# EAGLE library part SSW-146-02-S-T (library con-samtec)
THROUGH-HOLE .025" SQ POST SOCKET Source: Samtec SSW.pdf
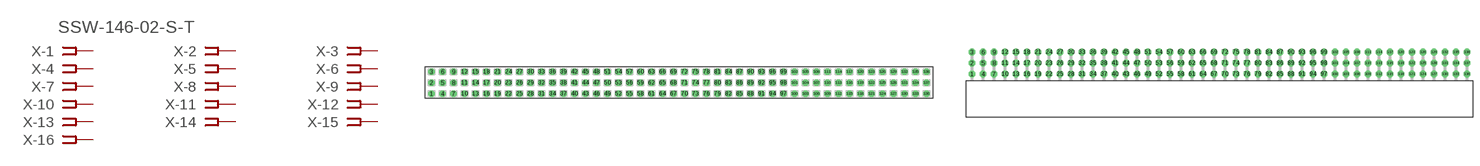
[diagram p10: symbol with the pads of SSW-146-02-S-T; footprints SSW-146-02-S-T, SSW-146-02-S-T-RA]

Designator prefix X; gates -1=FPINV -2=FPIN -3=FPIN -4=FPIN -5=FPIN -6=FPIN -7=FPIN -8=FPIN -9=FPIN -10=FPIN -11=FPIN -12=FPIN -13=FPIN -14=FPIN -15=FPIN -16=FPIN -17=FPIN -18=FPIN -19=FPIN -20=FPIN -21=FPIN -22=FPIN -23=FPIN -24=FPIN -25=FPIN -26=FPIN -27=FPIN -28=FPIN -29=FPIN -30=FPIN -31=FPIN -32=FPIN -33=FPIN -34=FPIN -35=FPIN -36=FPIN -37=FPIN -38=FPIN -39=FPIN -40=FPIN -41=FPIN -42=FPIN -43=FPIN -44=FPIN -45=FPIN -46=FPIN -47=FPIN -48=FPIN -49=FPIN -50=FPIN -51=FPIN -52=FPIN -53=FPIN -54=FPIN -55=FPIN -56=FPIN -57=FPIN -58=FPIN -59=FPIN -60=FPIN -61=FPIN -62=FPIN -63=FPIN -64=FPIN -65=FPIN -66=FPIN -67=FPIN -68=FPIN -69=FPIN -70=FPIN -71=FPIN -72=FPIN -73=FPIN -74=FPIN -75=FPIN -76=FPIN -77=FPIN -78=FPIN -79=FPIN -80=FPIN -81=FPIN -82=FPIN -83=FPIN -84=FPIN -85=FPIN -86=FPIN -87=FPIN -88=FPIN -89=FPIN -90=FPIN -91=FPIN -92=FPIN -93=FPIN -94=FPIN -95=FPIN -96=FPIN -97=FPIN -98=FPIN -99=FPIN -100=FPIN -101=FPIN -102=FPIN -103=FPIN -104=FPIN -105=FPIN -106=FPIN -107=FPIN -108=FPIN -109=FPIN -110=FPIN -111=FPIN -112=FPIN -113=FPIN -114=FPIN -115=FPIN -116=FPIN -117=FPIN -118=FPIN -119=FPIN -120=FPIN -121=FPIN -122=FPIN -123=FPIN -124=FPIN -125=FPIN -126=FPIN -127=FPIN -128=FPIN -129=FPIN -130=FPIN -131=FPIN -132=FPIN -133=FPIN -134=FPIN -135=FPIN -136=FPIN -137=FPIN -138=FPIN

## SSW-146-02-S-T (MPN: SSW-146-02-S-T; OC_FARNELL: unknown; OC_NEWARK: 83P1660)  [SSW-146-02-S-T]
1  -1:1  pas
2  -2:1  pas
3  -3:1  pas
4  -4:1  pas
5  -5:1  pas
6  -6:1  pas
7  -7:1  pas
8  -8:1  pas
9  -9:1  pas
10  -10:1  pas
11  -11:1  pas
12  -12:1  pas
13  -13:1  pas
14  -14:1  pas
15  -15:1  pas
16  -16:1  pas
17  -17:1  pas
18  -18:1  pas
19  -19:1  pas
20  -20:1  pas
21  -21:1  pas
22  -22:1  pas
23  -23:1  pas
24  -24:1  pas
25  -25:1  pas
26  -26:1  pas
27  -27:1  pas
28  -28:1  pas
29  -29:1  pas
30  -30:1  pas
31  -31:1  pas
32  -32:1  pas
33  -33:1  pas
34  -34:1  pas
35  -35:1  pas
36  -36:1  pas
37  -37:1  pas
38  -38:1  pas
39  -39:1  pas
40  -40:1  pas
41  -41:1  pas
42  -42:1  pas
43  -43:1  pas
44  -44:1  pas
45  -45:1  pas
46  -46:1  pas
47  -47:1  pas
48  -48:1  pas
49  -49:1  pas
50  -50:1  pas
51  -51:1  pas
52  -52:1  pas
53  -53:1  pas
54  -54:1  pas
55  -55:1  pas
56  -56:1  pas
57  -57:1  pas
58  -58:1  pas
59  -59:1  pas
60  -60:1  pas
61  -61:1  pas
62  -62:1  pas
63  -63:1  pas
64  -64:1  pas
65  -65:1  pas
66  -66:1  pas
67  -67:1  pas
68  -68:1  pas
69  -69:1  pas
70  -70:1  pas
71  -71:1  pas
72  -72:1  pas
73  -73:1  pas
74  -74:1  pas
75  -75:1  pas
76  -76:1  pas
77  -77:1  pas
78  -78:1  pas
79  -79:1  pas
80  -80:1  pas
81  -81:1  pas
82  -82:1  pas
83  -83:1  pas
84  -84:1  pas
85  -85:1  pas
86  -86:1  pas
87  -87:1  pas
88  -88:1  pas
89  -89:1  pas
90  -90:1  pas
91  -91:1  pas
92  -92:1  pas
93  -93:1  pas
94  -94:1  pas
95  -95:1  pas
96  -96:1  pas
97  -97:1  pas
98  -98:1  pas
99  -99:1  pas
100  -100:1  pas
101  -101:1  pas
102  -102:1  pas
103  -103:1  pas
104  -104:1  pas
105  -105:1  pas
106  -106:1  pas
107  -107:1  pas
108  -108:1  pas
109  -109:1  pas
110  -110:1  pas
111  -111:1  pas
112  -112:1  pas
113  -113:1  pas
114  -114:1  pas
115  -115:1  pas
116  -116:1  pas
117  -117:1  pas
118  -118:1  pas
119  -119:1  pas
120  -120:1  pas
121  -121:1  pas
122  -122:1  pas
123  -123:1  pas
124  -124:1  pas
125  -125:1  pas
126  -126:1  pas
127  -127:1  pas
128  -128:1  pas
129  -129:1  pas
130  -130:1  pas
131  -131:1  pas
132  -132:1  pas
133  -133:1  pas
134  -134:1  pas
135  -135:1  pas
136  -136:1  pas
137  -137:1  pas
138  -138:1  pas

## SSW-146-02-S-TRA (OC_FARNELL: unknown; OC_NEWARK: unknown)  [SSW-146-02-S-T-RA]
Pads as for SSW-146-02-S-T

## Footprint SSW-146-02-S-T (pad centres in mm)
THROUGH-HOLE .025" SQ POST SOCKET Source: Samtec SSW.pdf
drill 1 pad 1.5 octagon: 1 -57.15,-2.54; 2 -57.15,0; 3 -57.15,2.54; 4 -54.61,-2.54; 5 -54.61,0; 6 -54.61,2.54; 7 -52.07,-2.54; 8 -52.07,0; 9 -52.07,2.54; 10 -49.53,-2.54; 11 -49.53,0; 12 -49.53,2.54; 13 -46.99,-2.54; 14 -46.99,0; 15 -46.99,2.54; 16 -44.45,-2.54; 17 -44.45,0; 18 -44.45,2.54; 19 -41.91,-2.54; 20 -41.91,0; 21 -41.91,2.54; 22 -39.37,-2.54; 23 -39.37,0; 24 -39.37,2.54; 25 -36.83,-2.54; 26 -36.83,0; 27 -36.83,2.54; 28 -34.29,-2.54; 29 -34.29,0; 30 -34.29,2.54; 31 -31.75,-2.54; 32 -31.75,0; 33 -31.75,2.54; 34 -29.21,-2.54; 35 -29.21,0; 36 -29.21,2.54; 37 -26.67,-2.54; 38 -26.67,0; 39 -26.67,2.54; 40 -24.13,-2.54; 41 -24.13,0; 42 -24.13,2.54; 43 -21.59,-2.54; 44 -21.59,0; 45 -21.59,2.54; 46 -19.05,-2.54; 47 -19.05,0; 48 -19.05,2.54; 49 -16.51,-2.54; 50 -16.51,0; 51 -16.51,2.54; 52 -13.97,-2.54; 53 -13.97,0; 54 -13.97,2.54; 55 -11.43,-2.54; 56 -11.43,0; 57 -11.43,2.54; 58 -8.89,-2.54; 59 -8.89,0; 60 -8.89,2.54; 61 -6.35,-2.54; 62 -6.35,0; 63 -6.35,2.54; 64 -3.81,-2.54; 65 -3.81,0; 66 -3.81,2.54; 67 -1.27,-2.54; 68 -1.27,0; 69 -1.27,2.54; 70 1.27,-2.54; 71 1.27,0; 72 1.27,2.54; 73 3.81,-2.54; 74 3.81,0; 75 3.81,2.54; 76 6.35,-2.54; 77 6.35,0; 78 6.35,2.54; 79 8.89,-2.54; 80 8.89,0; 81 8.89,2.54; 82 11.43,-2.54; 83 11.43,0; 84 11.43,2.54; 85 13.97,-2.54; 86 13.97,0; 87 13.97,2.54; 88 16.51,-2.54; 89 16.51,0; 90 16.51,2.54; 91 19.05,-2.54; 92 19.05,0; 93 19.05,2.54; 94 21.59,-2.54; 95 21.59,0; 96 21.59,2.54; 97 24.13,-2.54; 98 24.13,0; 99 24.13,2.54; 100 26.67,-2.54; 101 26.67,0; 102 26.67,2.54; 103 29.21,-2.54; 104 29.21,0; 105 29.21,2.54; 106 31.75,-2.54; 107 31.75,0; 108 31.75,2.54; 109 34.29,-2.54; 110 34.29,0; 111 34.29,2.54; 112 36.83,-2.54; 113 36.83,0; 114 36.83,2.54; 115 39.37,-2.54; 116 39.37,0; 117 39.37,2.54; 118 41.91,-2.54; 119 41.91,0; 120 41.91,2.54; 121 44.45,-2.54; 122 44.45,0; 123 44.45,2.54; 124 46.99,-2.54; 125 46.99,0; 126 46.99,2.54; 127 49.53,-2.54; 128 49.53,0; 129 49.53,2.54; 130 52.07,-2.54; 131 52.07,0; 132 52.07,2.54; 133 54.61,-2.54; 134 54.61,0; 135 54.61,2.54; 136 57.15,-2.54; 137 57.15,0; 138 57.15,2.54

## Footprint SSW-146-02-S-T-RA (pad centres in mm)
THROUGH-HOLE .025" SQ POST SOCKET Source: Samtec SSW.pdf
drill 1 pad 1.5 octagon: 1 -57.15,1.524; 2 -57.15,4.064; 3 -57.15,6.604; 4 -54.61,1.524; 5 -54.61,4.064; 6 -54.61,6.604; 7 -52.07,1.524; 8 -52.07,4.064; 9 -52.07,6.604; 10 -49.53,1.524; 11 -49.53,4.064; 12 -49.53,6.604; 13 -46.99,1.524; 14 -46.99,4.064; 15 -46.99,6.604; 16 -44.45,1.524; 17 -44.45,4.064; 18 -44.45,6.604; 19 -41.91,1.524; 20 -41.91,4.064; 21 -41.91,6.604; 22 -39.37,1.524; 23 -39.37,4.064; 24 -39.37,6.604; 25 -36.83,1.524; 26 -36.83,4.064; 27 -36.83,6.604; 28 -34.29,1.524; 29 -34.29,4.064; 30 -34.29,6.604; 31 -31.75,1.524; 32 -31.75,4.064; 33 -31.75,6.604; 34 -29.21,1.524; 35 -29.21,4.064; 36 -29.21,6.604; 37 -26.67,1.524; 38 -26.67,4.064; 39 -26.67,6.604; 40 -24.13,1.524; 41 -24.13,4.064; 42 -24.13,6.604; 43 -21.59,1.524; 44 -21.59,4.064; 45 -21.59,6.604; 46 -19.05,1.524; 47 -19.05,4.064; 48 -19.05,6.604; 49 -16.51,1.524; 50 -16.51,4.064; 51 -16.51,6.604; 52 -13.97,1.524; 53 -13.97,4.064; 54 -13.97,6.604; 55 -11.43,1.524; 56 -11.43,4.064; 57 -11.43,6.604; 58 -8.89,1.524; 59 -8.89,4.064; 60 -8.89,6.604; 61 -6.35,1.524; 62 -6.35,4.064; 63 -6.35,6.604; 64 -3.81,1.524; 65 -3.81,4.064; 66 -3.81,6.604; 67 -1.27,1.524; 68 -1.27,4.064; 69 -1.27,6.604; 70 1.27,1.524; 71 1.27,4.064; 72 1.27,6.604; 73 3.81,1.524; 74 3.81,4.064; 75 3.81,6.604; 76 6.35,1.524; 77 6.35,4.064; 78 6.35,6.604; 79 8.89,1.524; 80 8.89,4.064; 81 8.89,6.604; 82 11.43,1.524; 83 11.43,4.064; 84 11.43,6.604; 85 13.97,1.524; 86 13.97,4.064; 87 13.97,6.604; 88 16.51,1.524; 89 16.51,4.064; 90 16.51,6.604; 91 19.05,1.524; 92 19.05,4.064; 93 19.05,6.604; 94 21.59,1.524; 95 21.59,4.064; 96 21.59,6.604; 97 24.13,1.524; 98 24.13,4.064; 99 24.13,6.604; 100 26.67,1.524; 101 26.67,4.064; 102 26.67,6.604; 103 29.21,1.524; 104 29.21,4.064; 105 29.21,6.604; 106 31.75,1.524; 107 31.75,4.064; 108 31.75,6.604; 109 34.29,1.524; 110 34.29,4.064; 111 34.29,6.604; 112 36.83,1.524; 113 36.83,4.064; 114 36.83,6.604; 115 39.37,1.524; 116 39.37,4.064; 117 39.37,6.604; 118 41.91,1.524; 119 41.91,4.064; 120 41.91,6.604; 121 44.45,1.524; 122 44.45,4.064; 123 44.45,6.604; 124 46.99,1.524; 125 46.99,4.064; 126 46.99,6.604; 127 49.53,1.524; 128 49.53,4.064; 129 49.53,6.604; 130 52.07,1.524; 131 52.07,4.064; 132 52.07,6.604; 133 54.61,1.524; 134 54.61,4.064; 135 54.61,6.604; 136 57.15,1.524; 137 57.15,4.064; 138 57.15,6.604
